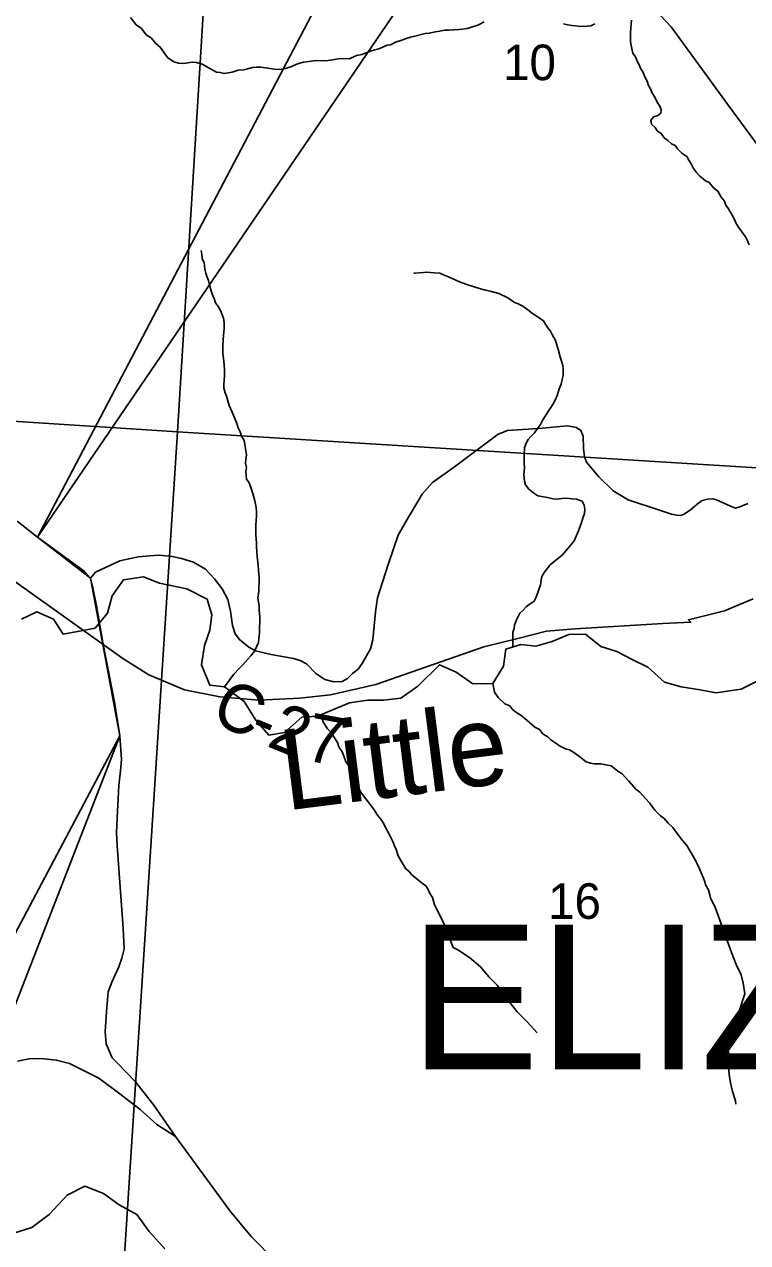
# Model space of a CAD drawing. Extents: x 0 to 34, y 0 to 22.
# Drawn here: x 5.204 to 6.055, y 16.547 to 17.98 of the extents above; entities that cross this region are included whole.
import ezdxf

# ---------------------------------------------------------------- set-up
doc = ezdxf.new("R2010")
doc.units = 0
for name, color, linetype in [('GM_X_County_Road', 7, 'Continuous'), ('GM_X_County_Road_Text', 7, 'Continuous'), ('GM_X_Minor_River', 7, 'Continuous'), ('GM_X_Minor_River_Text', 7, 'Continuous'), ('GM_X_Rail_Line', 7, 'Continuous'), ('GM_X_Section', 7, 'Continuous'), ('GM_X_Section_Text', 7, 'Continuous'), ('GM_X_State_Route', 7, 'Continuous'), ('GM_X_Township_Road', 7, 'Continuous'), ('GM_X_Township_Text', 7, 'Continuous'), ('SH_Data', 7, 'Continuous'), ('SH_Text', 7, 'Continuous')]:
    doc.layers.add(name, color=color, linetype=linetype)

msp = doc.modelspace()

# ---------------------------------------------------------------- linework, layer by layer
at = {"layer": 'GM_X_County_Road'}
for points in [[(5.2814, 17.3287), (5.2874, 17.3357), (5.3042, 17.3438), (5.3161, 17.3491), (5.3265, 17.3517), (5.3379, 17.3538), (5.3507, 17.3552), (5.3621, 17.3558), (5.3776, 17.3543), (5.3886, 17.352), (5.4028, 17.3477), (5.4166, 17.3392), (5.4274, 17.3281), (5.4365, 17.3164), (5.4429, 17.3038), (5.4461, 17.29), (5.4485, 17.2733), (5.4517, 17.2634), (5.4567, 17.2566), (5.4678, 17.2478), (5.4757, 17.2434), (5.4942, 17.2391), (5.5202, 17.2344), (5.5281, 17.232), (5.5355, 17.2279), (5.5466, 17.2168), (5.5574, 17.2095), (5.568, 17.2068), (5.5776, 17.2074), (5.5838, 17.2106), (5.5899, 17.2165), (5.5964, 17.2218), (5.6013, 17.2285), (5.611, 17.2455), (5.6136, 17.2563), (5.6169, 17.2891), (5.6193, 17.3056), (5.6317, 17.3447), (5.6436, 17.3792), (5.6519, 17.394), (5.6717, 17.4277), (5.6841, 17.4413), (5.7099, 17.4597), (5.7611, 17.4981), (5.7674, 17.5007), (5.772, 17.5023), (5.8086, 17.5049), (5.8428, 17.508), (5.8534, 17.5062), (5.8586, 17.5025), (5.8612, 17.4958), (5.8617, 17.4818), (5.8627, 17.4714), (5.8651, 17.4652), (5.8798, 17.4478), (5.8967, 17.4317), (5.9143, 17.4211), (5.9523, 17.4085), (5.9654, 17.4042), (5.9716, 17.403), (5.9759, 17.4026), (5.9792, 17.4036), (5.9874, 17.4089), (5.9955, 17.4159), (6.0013, 17.4201), (6.0078, 17.4219), (6.0141, 17.422), (6.0183, 17.4208), (6.0347, 17.4133), (6.0405, 17.4113), (6.0456, 17.4126), (6.0551, 17.4168)], [(5.1954, 16.7608), (5.2091, 16.7635), (5.2233, 16.7637), (5.2411, 16.762), (5.2569, 16.7579), (5.2914, 16.7407), (5.3159, 16.7223), (5.3399, 16.7037), (5.3595, 16.6862), (5.3813, 16.6721)]]:
    msp.add_lwpolyline(points, dxfattribs=at)
at = {"layer": 'GM_X_Minor_River'}
for points in [[(5.7447, 17.9834), (5.7375, 17.9793), (5.7287, 17.9764), (5.7249, 17.9753), (5.7188, 17.9746), (5.715, 17.9743), (5.7032, 17.9736), (5.6979, 17.9733), (5.6926, 17.9723), (5.6873, 17.9716), (5.6801, 17.9698), (5.6755, 17.9694), (5.6633, 17.9665), (5.658, 17.9651), (5.6542, 17.964), (5.6466, 17.9611), (5.6405, 17.9592), (5.6344, 17.9563), (5.6306, 17.9556), (5.6207, 17.9515), (5.6161, 17.9501), (5.6108, 17.9486), (5.6047, 17.9464), (5.6009, 17.9449), (5.5944, 17.9435), (5.5864, 17.9398), (5.5818, 17.9399), (5.5731, 17.9396), (5.5666, 17.9385), (5.561, 17.9378), (5.5553, 17.9375), (5.5458, 17.9377), (5.5389, 17.9366), (5.5321, 17.9359), (5.5264, 17.9341), (5.5214, 17.9323), (5.5161, 17.9297), (5.5104, 17.9282), (5.5047, 17.9272), (5.4975, 17.9276), (5.4903, 17.9289), (5.4819, 17.9297), (5.4766, 17.9298), (5.4721, 17.9295), (5.4679, 17.9284), (5.4618, 17.9269), (5.4553, 17.9263), (5.4481, 17.9241), (5.4386, 17.9223), (5.4341, 17.9235), (5.4299, 17.9239), (5.4261, 17.9259), (5.419, 17.9298), (5.4129, 17.9333), (5.4061, 17.9353), (5.4012, 17.9357), (5.3959, 17.935), (5.3913, 17.9343), (5.3849, 17.9344), (5.3796, 17.9363), (5.3721, 17.9414), (5.3695, 17.9452), (5.3635, 17.9536), (5.3582, 17.9579), (5.3534, 17.964), (5.347, 17.9679), (5.3413, 17.9752), (5.3353, 17.9795), (5.3286, 17.9883)], [(5.8752, 17.981), (5.8702, 17.9787), (5.8626, 17.9777), (5.8558, 17.9782), (5.8482, 17.979), (5.8429, 17.9798), (5.838, 17.981)], [(5.9417, 17.8627), (5.941, 17.8673), (5.9441, 17.8714), (5.9491, 17.8732), (5.9529, 17.8759), (5.9533, 17.8797), (5.9515, 17.8842), (5.9485, 17.8888), (5.9455, 17.8946), (5.9422, 17.8999), (5.9407, 17.9045), (5.9381, 17.9083), (5.9366, 17.9133), (5.9337, 17.9187), (5.9318, 17.9236), (5.9288, 17.9286), (5.9274, 17.9328), (5.9244, 17.9378), (5.9229, 17.942), (5.9199, 17.9462), (5.9188, 17.95), (5.9171, 17.9595), (5.9172, 17.9705), (5.9176, 17.9759), (5.9181, 17.985)], [(6.0566, 17.721), (6.0547, 17.7256), (6.0525, 17.7302), (6.048, 17.7363), (6.0443, 17.7417), (6.0413, 17.7459), (6.0391, 17.7513), (6.0365, 17.7559), (6.0324, 17.7631), (6.0294, 17.7674), (6.0276, 17.7723), (6.0238, 17.7769), (6.0197, 17.7842), (6.0149, 17.7881), (6.0096, 17.7942), (6.0051, 17.7962), (5.9987, 17.8016), (5.9946, 17.8058), (5.9912, 17.8108), (5.9886, 17.8161), (5.9856, 17.8204), (5.9834, 17.8249), (5.9774, 17.8288), (5.9725, 17.8338), (5.9695, 17.8377), (5.9654, 17.8396), (5.9609, 17.8435), (5.9567, 17.8469), (5.953, 17.8519), (5.9485, 17.855), (5.9459, 17.8589), (5.9417, 17.8627)], [(5.4392, 17.2009), (5.4502, 17.2158), (5.4567, 17.223), (5.4606, 17.2267), (5.4667, 17.2335), (5.4702, 17.2376), (5.4744, 17.2429), (5.4771, 17.2489), (5.4791, 17.2531), (5.4795, 17.258), (5.4803, 17.2645), (5.4806, 17.2835), (5.4799, 17.2915), (5.48, 17.2968), (5.4792, 17.3006), (5.4785, 17.3051), (5.4794, 17.3135), (5.4794, 17.3184), (5.4799, 17.3234), (5.48, 17.3294), (5.4793, 17.3378), (5.4786, 17.3439), (5.4776, 17.3542), (5.477, 17.366), (5.477, 17.3701), (5.4763, 17.3751), (5.476, 17.3796), (5.4761, 17.3903), (5.4766, 17.3975), (5.477, 17.4013), (5.4767, 17.407), (5.4764, 17.4119), (5.4749, 17.4196), (5.4738, 17.4241), (5.472, 17.4295), (5.4705, 17.4344), (5.468, 17.4409), (5.465, 17.4451), (5.4643, 17.4543), (5.4651, 17.4588), (5.4637, 17.4641), (5.4641, 17.4683), (5.4649, 17.474), (5.4642, 17.4786), (5.4635, 17.4839), (5.4621, 17.4908), (5.4591, 17.4957), (5.4577, 17.5011), (5.4554, 17.5057), (5.4532, 17.5118), (5.4481, 17.524), (5.4462, 17.5282), (5.4447, 17.532), (5.4429, 17.5374), (5.4414, 17.5427), (5.44, 17.5469), (5.4385, 17.5522), (5.4382, 17.5568), (5.4386, 17.561), (5.4391, 17.5674), (5.4391, 17.5735), (5.4388, 17.5796), (5.4378, 17.5872), (5.4371, 17.5929), (5.4372, 17.6013), (5.4377, 17.6096), (5.4385, 17.6187), (5.4389, 17.6225), (5.4386, 17.629), (5.4379, 17.6347), (5.4365, 17.6385), (5.435, 17.6427), (5.432, 17.6481), (5.4287, 17.6527), (5.4268, 17.6576), (5.425, 17.6622), (5.4235, 17.6668), (5.4217, 17.6721), (5.4203, 17.679), (5.4188, 17.6828), (5.4173, 17.6874), (5.4159, 17.6923), (5.4152, 17.7), (5.413, 17.7045), (5.4126, 17.7095), (5.4116, 17.7141)], [(5.7786, 17.248), (5.7785, 17.2649), (5.7801, 17.2698), (5.7805, 17.2736), (5.7829, 17.2796), (5.7868, 17.2875), (5.7906, 17.2913), (5.7941, 17.295), (5.7979, 17.298), (5.8036, 17.3018), (5.8059, 17.3063), (5.811, 17.3211), (5.8119, 17.3267), (5.8127, 17.3309), (5.8154, 17.3354), (5.8223, 17.3445), (5.8311, 17.3516), (5.8365, 17.3557), (5.8438, 17.3639), (5.8507, 17.3726), (5.8558, 17.3843), (5.8593, 17.3941), (5.8613, 17.4006), (5.8629, 17.4047), (5.8633, 17.41), (5.8626, 17.4146), (5.86, 17.4192), (5.8536, 17.4216), (5.8479, 17.422), (5.8422, 17.4229), (5.8361, 17.4226), (5.8308, 17.4219), (5.8255, 17.4223), (5.8194, 17.4235), (5.8081, 17.4256), (5.8043, 17.4279), (5.7972, 17.4333), (5.7934, 17.4387), (5.7923, 17.4429), (5.7913, 17.4512), (5.7921, 17.4584), (5.7918, 17.4638), (5.7919, 17.474), (5.7924, 17.482), (5.7944, 17.4877), (5.7967, 17.4918), (5.7998, 17.4956), (5.804, 17.4997), (5.8075, 17.505), (5.8109, 17.5095), (5.814, 17.5152), (5.8202, 17.525), (5.8233, 17.5295), (5.826, 17.534), (5.8287, 17.5389), (5.8307, 17.5438), (5.8331, 17.5514), (5.8354, 17.5571), (5.8366, 17.5624), (5.8378, 17.5673), (5.8379, 17.5749), (5.8375, 17.5791), (5.8361, 17.5829), (5.8346, 17.5875), (5.8321, 17.5966), (5.8288, 17.6084), (5.8251, 17.6146), (5.8228, 17.6195), (5.8195, 17.6238), (5.8146, 17.6314), (5.806, 17.6372), (5.8018, 17.6403), (5.7962, 17.6446), (5.7902, 17.6488), (5.7841, 17.6519), (5.7804, 17.6531), (5.7728, 17.6585), (5.7619, 17.6636), (5.7517, 17.6664), (5.7464, 17.6676), (5.7403, 17.6692), (5.732, 17.672), (5.7256, 17.674), (5.7199, 17.6759), (5.7158, 17.6775), (5.7116, 17.6795), (5.7078, 17.681), (5.7007, 17.6842), (5.6969, 17.6857), (5.6924, 17.6877), (5.6859, 17.6881), (5.6772, 17.6886), (5.6734, 17.6883), (5.6635, 17.6877), (5.6618, 17.6876)], [(6.0661, 17.2078), (6.0474, 17.1984), (6.0174, 17.194), (5.9989, 17.1975), (5.9765, 17.2011), (5.9572, 17.2065), (5.9376, 17.224), (5.9183, 17.2336), (5.901, 17.2425), (5.882, 17.2486), (5.8639, 17.2628), (5.8446, 17.2625), (5.8248, 17.2543), (5.8054, 17.2487), (5.788, 17.2507), (5.7702, 17.2451), (5.7674, 17.2253), (5.7551, 17.2049), (5.7316, 17.2046), (5.712, 17.2184), (5.6923, 17.2269), (5.6667, 17.2019), (5.6465, 17.1876), (5.6264, 17.1851), (5.6078, 17.1852), (5.5862, 17.1822), (5.5676, 17.1744), (5.5485, 17.1665), (5.5303, 17.1651), (5.5097, 17.1473), (5.4915, 17.144), (5.4761, 17.1616), (5.4622, 17.1836), (5.4392, 17.2009), (5.4218, 17.2028), (5.4121, 17.2268), (5.4156, 17.2496), (5.4218, 17.2678), (5.4242, 17.2856), (5.4186, 17.3039), (5.3948, 17.3161), (5.3626, 17.3228), (5.3437, 17.3305), (5.3202, 17.3268), (5.3068, 17.3079), (5.3014, 17.2878), (5.2868, 17.27), (5.2663, 17.2659), (5.2492, 17.263), (5.238, 17.2805), (5.2183, 17.2893), (5.2004, 17.2807)], [(5.7551, 17.2049), (5.7569, 17.1945), (5.7613, 17.1883), (5.7692, 17.181), (5.7749, 17.1787), (5.7786, 17.174), (5.7843, 17.1694), (5.788, 17.1675), (5.7948, 17.1617), (5.8046, 17.1536), (5.8098, 17.1509), (5.8143, 17.1451), (5.8196, 17.142), (5.8234, 17.1385), (5.8279, 17.1354), (5.8335, 17.1316), (5.8407, 17.128), (5.8452, 17.1268), (5.8505, 17.1237), (5.8558, 17.1199), (5.8595, 17.1172), (5.8648, 17.1129), (5.8701, 17.111), (5.8743, 17.1105), (5.8818, 17.1104), (5.8943, 17.108), (5.9022, 17.1018), (5.9071, 17.0987), (5.915, 17.0899), (5.9232, 17.0806), (5.9281, 17.0772), (5.9345, 17.0695), (5.9394, 17.0645), (5.9457, 17.056), (5.9525, 17.0491), (5.9562, 17.0464), (5.9615, 17.0406), (5.9667, 17.0353), (5.9708, 17.0299), (5.9783, 17.0203), (5.9832, 17.0145), (5.9861, 17.0096), (5.991, 17.0008), (5.9936, 16.9965), (5.9954, 16.9927), (5.9984, 16.987), (6.0002, 16.982), (6.0028, 16.9759), (6.0047, 16.9717), (6.0054, 16.9679), (6.0087, 16.9622), (6.0102, 16.9561), (6.0113, 16.9522), (6.0142, 16.9465), (6.0168, 16.9412), (6.0188, 16.9361)], [(5.5521, 17.1678), (5.5558, 17.159), (5.5602, 17.1514), (5.564, 17.1479), (5.5688, 17.141), (5.5722, 17.1356), (5.5736, 17.1303), (5.5777, 17.1246), (5.58, 17.1188), (5.5818, 17.1127), (5.5866, 17.1066), (5.5888, 17.0993), (5.5918, 17.0951), (5.594, 17.0875), (5.5966, 17.0825), (5.6003, 17.076), (5.6056, 17.0691), (5.6145, 17.0576), (5.6194, 17.0499), (5.6231, 17.0453), (5.6265, 17.04), (5.6287, 17.0354), (5.6328, 17.0277), (5.6354, 17.0231), (5.6372, 17.0189), (5.6394, 17.014), (5.6413, 17.0098), (5.6435, 17.0021), (5.6465, 16.9968), (5.6502, 16.9907), (5.6524, 16.9868), (5.6562, 16.9841), (5.6592, 16.9803), (5.6682, 16.9726), (5.6723, 16.9695), (5.6761, 16.9668), (5.6787, 16.9626), (5.6805, 16.9587), (5.6839, 16.953), (5.6864, 16.9446), (5.6913, 16.9347), (5.6935, 16.9305), (5.6957, 16.9262), (5.6972, 16.9224), (5.6979, 16.9207)], [(6.036, 16.8885), (6.0188, 16.9361)], [(5.708, 16.8947), (5.7081, 16.8944), (5.6979, 16.9207)], [(5.7081, 16.8944), (5.7138, 16.8914), (5.7274, 16.8827), (5.7403, 16.8714), (5.7505, 16.8596), (5.7599, 16.8501), (5.7709, 16.8346), (5.7838, 16.8187), (5.7955, 16.8069), (5.8073, 16.794)], [(6.036, 16.8885), (6.0412, 16.8742), (6.0472, 16.862), (6.0495, 16.8525), (6.0514, 16.8397)], [(6.0514, 16.8397), (6.0446, 16.8184), (6.0431, 16.8081), (6.0374, 16.7983), (6.0339, 16.7884), (6.032, 16.7786), (6.0324, 16.7653), (6.0323, 16.7547), (6.0331, 16.7448), (6.0349, 16.735), (6.0372, 16.7251), (6.0406, 16.7141), (6.0409, 16.7099)], [(5.0867, 16.5428), (5.1083, 16.5493), (5.1268, 16.5477), (5.1469, 16.5489), (5.1719, 16.5549), (5.1924, 16.5587), (5.2124, 16.5648), (5.2329, 16.5803), (5.2538, 16.6031), (5.2746, 16.6134), (5.2966, 16.605), (5.3151, 16.5917), (5.3359, 16.5802), (5.3506, 16.5601), (5.3691, 16.5399)]]:
    msp.add_lwpolyline(points, dxfattribs=at)
at = {"layer": 'GM_X_Rail_Line'}
msp.add_lwpolyline([(6.0614, 17.3045), (6.0277, 17.2904), (5.9851, 17.2798), (5.9879, 17.277), (5.9549, 17.2754), (5.852, 17.269), (5.8182, 17.2666), (5.7844, 17.2577), (5.7442, 17.2481), (5.6171, 17.2038), (5.564, 17.1917), (5.5278, 17.1877), (5.4796, 17.1853), (5.4337, 17.1893), (5.3919, 17.1974), (5.3501, 17.2151), (5.3195, 17.2344), (5.0671, 17.4139)], dxfattribs=at)
at = {"layer": 'GM_X_Section'}
for points in [[(4.4314, 18.5943), (5.4469, 18.529), (5.3838, 17.5009), (4.383, 17.5655)], [(5.4469, 18.529), (6.4594, 18.4632), (6.388, 17.4386), (5.3838, 17.5009)], [(4.383, 17.5655), (5.3838, 17.5009), (5.3178, 16.4777), (4.3194, 16.5337)], [(5.3838, 17.5009), (6.388, 17.4386), (6.3205, 16.4222), (5.3178, 16.4777)]]:
    msp.add_lwpolyline(points, close=True, dxfattribs=at)
at = {"layer": 'GM_X_State_Route'}
msp.add_lwpolyline([(5.4991, 16.5253), (5.4709, 16.5538), (5.4459, 16.5842), (5.3813, 16.6721), (5.3559, 16.709), (5.3344, 16.7362), (5.3129, 16.7585), (5.3071, 16.7646), (5.3, 16.7811), (5.2988, 16.795), (5.3004, 16.8187), (5.3024, 16.8423), (5.3067, 16.8534), (5.3146, 16.8716), (5.3183, 16.8819), (5.3209, 16.8927), (5.3198, 16.917), (5.3127, 17.0139), (5.312, 17.0292), (5.3127, 17.047), (5.3148, 17.085), (5.3169, 17.102), (5.318, 17.1156), (5.3159, 17.1435), (5.3095, 17.1828), (5.2961, 17.2531), (5.2886, 17.2963), (5.2839, 17.3194), (5.2814, 17.3287), (5.2741, 17.337), (5.2191, 17.3772), (5.195, 17.3957)], dxfattribs=at)
at = {"layer": 'GM_X_Township_Road'}
msp.add_lwpolyline([(6.1533, 17.6932), (6.1455, 17.7183), (6.1321, 17.7496), (6.031, 17.8864), (5.9649, 17.9774), (5.8325, 18.118), (5.6892, 18.2779), (5.5706, 18.3854), (5.4769, 18.4764), (5.3776, 18.6004)], dxfattribs=at)
at = {"layer": 'SH_Data'}
msp.add_lwpolyline([(5.2191, 17.3772), (5.2814, 17.3287), (5.3159, 17.1435)], dxfattribs=at)
at = {"layer": 'SH_Text'}
for points in [[(7.0694, 20.091), (7.0694, 20.9), (5.2191, 17.3772)], [(4.1319, 14.1), (4.1319, 14.9089), (5.3159, 17.1435)]]:
    msp.add_lwpolyline(points, close=True, dxfattribs=at)

# ---------------------------------------------------------------- texts
at = {"layer": 'GM_X_County_Road_Text'}
for s, rotation, p in [('C', 335.5073, (5.421, 17.1611)), ('2', 337.9096, (5.4874, 17.1317)), ('7', 349.5085, (5.5319, 17.115)), ('-', 337.3378, (5.4653, 17.1409))]:
    msp.add_text(s, height=0.0568, rotation=rotation, dxfattribs=at).set_placement(p)
at = {"layer": 'GM_X_Minor_River_Text'}
msp.add_text('Little', height=0.09469, rotation=7.2298, dxfattribs=at).set_placement((5.5113, 17.0553))
at = {"layer": 'GM_X_Section_Text'}
for s, p in [('10', (5.767, 17.9146)), ('16', (5.82, 16.928))]:
    msp.add_text(s, height=0.04186, rotation=0, dxfattribs=at).set_placement(p)
at = {"layer": 'GM_X_Township_Text'}
msp.add_text('ELIZABETH', height=0.17045, rotation=0, dxfattribs=at).set_placement((5.6574, 16.7509))

doc.saveas('drawing.dxf')
